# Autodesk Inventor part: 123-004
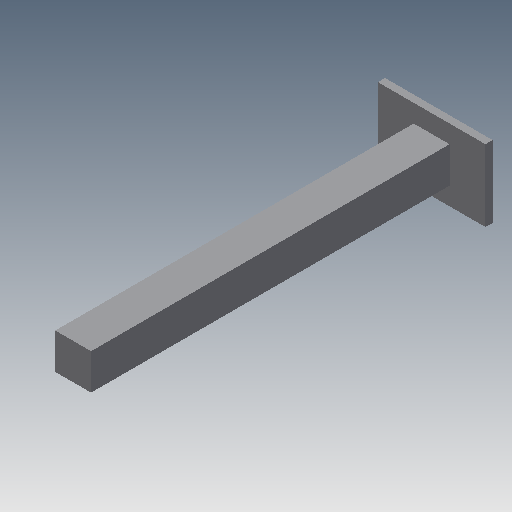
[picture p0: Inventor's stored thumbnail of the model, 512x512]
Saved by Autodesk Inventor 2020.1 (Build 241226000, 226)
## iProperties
Created: 2005-09
Part Number: 123-004
Document SubType Name: Modeling
Description: Podpora
Density: 1 g/cm^3
Material: Ogólny
Appearance: Domyślna
Mass: 1400 g
Surface Area: 1350 cm^2
Volume: 1400 cm^3
Designer: F.Stasiak
Manager: www.cadconsulting.pl
Company: Fabian Stasiak CAD Consulting
Author: F.Stasiak
Subject: Zbiór ćwiczeń. Autodesk Inventor 2020. Kurs podstawowy
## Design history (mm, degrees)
sketch "Szkic1"
  geometry: L1 (-75, 50)-(75, 50); L2 (75, 50)-(75, -50); L3 (75, -50)-(-75, -50); L4 (-75, -50)-(-75, 50); L5 (0, 50)-(0, -50); 2 further points
  constraints: 10 end point, 3 midpoint, 2 parallel, 1 coincident, 1 horizontal, 1 perpendicular
  dimensions: "d0" = 150 distance of L2.end L3.end; "d1" = 100 distance of L1.end L2.end
extrude "Wyciągnięcie proste1" new body sketch "Szkic1" distance "d2" = 10; taper "d3" = 0 deg
sketch "Szkic2"
  geometry: L1 (75, 50)-(75, -50) reference; L2 (-75, 50)-(75, 50) reference; L3 (-75, -50)-(-75, 50) reference; L4 (75, -50)-(-75, -50) reference; L5 (-25, 25)-(25, 25); L6 (25, 25)-(25, -25); L7 (25, -25)-(-25, -25); L8 (-25, -25)-(-25, 25); L9 (-25, -25)-(25, 25); L10 (0, 50)-(0, -50); 1 further point
  constraints: 12 end point, 4 midpoint, 2 parallel, 1 horizontal, 1 perpendicular
  dimensions: "d4" = 50 distance of L6.end L7.end; "d5" = 50 distance of L5.end L6.end (= d4)
extrude "Wyciągnięcie proste2" join sketch "Szkic2" distance "d7" = 500 (= WYSOKOŚĆ); taper "d8" = 0 deg
node "Bryła1"
node "Korpusy bryłowe"
node "Korpusy powierzchniowe"
node "Pętla rzutowana1"
other parameters: "WYSOKOŚĆ" = 500 [user parameter; used in 1 equation term]
